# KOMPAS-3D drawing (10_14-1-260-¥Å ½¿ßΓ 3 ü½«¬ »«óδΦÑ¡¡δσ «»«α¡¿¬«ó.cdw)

Views: Вид А, Вид 1, Вид 2
Referenced files in Y:\Информация\Оборудование\1 ЭП\04 Разъединители\ГК СЭЩ\РНК-110\: Для информации РНК-110.jpg
Referenced files: 07.10-2-260-ЭП лист 3.cdw
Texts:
  Текст на чертеже
  Размерные надписи
  Шероховатость
  Линия-выноска #1
  Линия-выноска #2
  Линия-выноска #3
  Отклонения формы и база
  Заголовок таблицы
  Ячейка таблицы
  Стрелка вида
  Обозначение изменения
  Фигурная скобка
  Номер узла
  Марка координационной оси
  VRCB
  Выносная надпись
  Обозначение узла
  Марка/позиционное обозначение с линией-выноской
  Марка/позиционное обозначение на линии
  Марка/позиционное обозначение без линии-выноски
  Normal
  txt
  Body Text
  heading 1
  Знак Знак Знак Знак Знак Знак
  Verdana
  Лит-Масса-Масштаб
  Материал-Предприятие
  MS Sans Serif
  Simplex
  Txt
  Title Specification
  Body Specification ( left align )
  Body Specificaton ( centered )
  Без имени
  Additional DXF text style 0
  Обычный
  Термин
  Список определений
  Адрес
  Цитаты
  Форматированный
  Courier New
  Z-конец формы
  Z-начало формы
  ТекстШаг1
  Денис
  heading 2
  AGOpus
  footer
  Title
  ООббыыччнныыйй
  Definition Term
  Definition List
  Address
  Blockquote
  Preformatted
  z-Bottom of Form
  z-Top of Form
  TXT
  header
  heading 8
  heading 3
  heading 6
  heading 7
  russ
  ТТееррммиинн
  ССппииссоокк ооппррееддееллеенниийй
  ААддрреесс
  ЦЦииттааттыы
  ФФооррммааттиирроовваанннныыйй
  Z-ккооннеецц ффооррммыы
  Z-ннааччааллоо ффооррммыы
  Абзац Знак
  heading 4
  heading 5
  heading 9
  GOST 2.304 type A
  rustxt
  цепи
  ссылки
  Маркировка
  Подпись в квадратике
  табл
  ЗОНА_привяз
  маркировка
  ГОСТ_МНЕ
  ESK - Обозначение
  текст переноса
  Тексты. 3,2
  Body Text 3
  клеммы, контакты
  тексты табл
  ISOCP
  Шрифт 2.5
  Заголовки
  RUSTXT
  style2
  HeliosLight
  Pa3
  Pa1
  NormalParagraphStyle
  Три с половиной
  Table Contents
  Table Heading
  CNBNDG+TimesNewRoman
  Subtitle
  ROMANS
  SIMPLEX
  Обычный (веб)
  Слой 1
  Поз.
  Кол.
  ед., кг
  Приме-
  чание
  ГОСТ Р 52082-03
  Изолятор опорный
  ИОС-10-2000 УХЛ1
  см. п.п. 2
  Примечания:
  Выполнить антикоррозийную защиту металлоконструкций методом горячего цинкования;
  Опорный изолятор (поз.1) входит в поставку ЗАО ГК "Электрощит" ТМ Самара.
  Разметка отверстий
  для крепления
  изолятора
  K5LT_AXLED_RGB_255_128_0_SC_1_THICK_0.18
  K5LT_THIN_RGB_0_0_0_THICK_0.18
  K5LT_BASIC_RGB_0_0_255_THICK_0.6
  Н.контр.
  Блок опорных изоляторов 6 кВ
  Разраб.
  Скахин
  Реконструкция ПС 110 кВ Опорная
  (замена трансформаторов 16МВА на 40МВА)
  Ведомость эскизного проекта
Dimensions and other numbers on the sheet: 10/14-1-260-ЭП; 7; 3.5; 2.5; 2,5; 1,8; 2.5 курсив; 2,5_3; 3,2 (надписи); 3,5_01; 2,5_01; 3,5_tabl; 5_заголовок; 2,3_; 3,2_; 3,2_зона не привяз; 2,5 грязносинь; 2,5 (контакты, клеммы); 5,0_белый_подчёркнутый; 3,2; 3.2 фиол; 3,5; 5; 3,2 элементы; 3,2 линия; 3,2 таблица; 3.2 маркировка; 2.5_Э5_надписи; 2.5_Э5_ссылки; 2.5_кабель; 3.2; 2.5 надписи; 3,2 (Зоны); 3 и 5; 1; 3; 26; 3280; 1000; 4 отв.; 18; 160; 204; 1700; 07/10-2-260-ЭП-; 11.12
